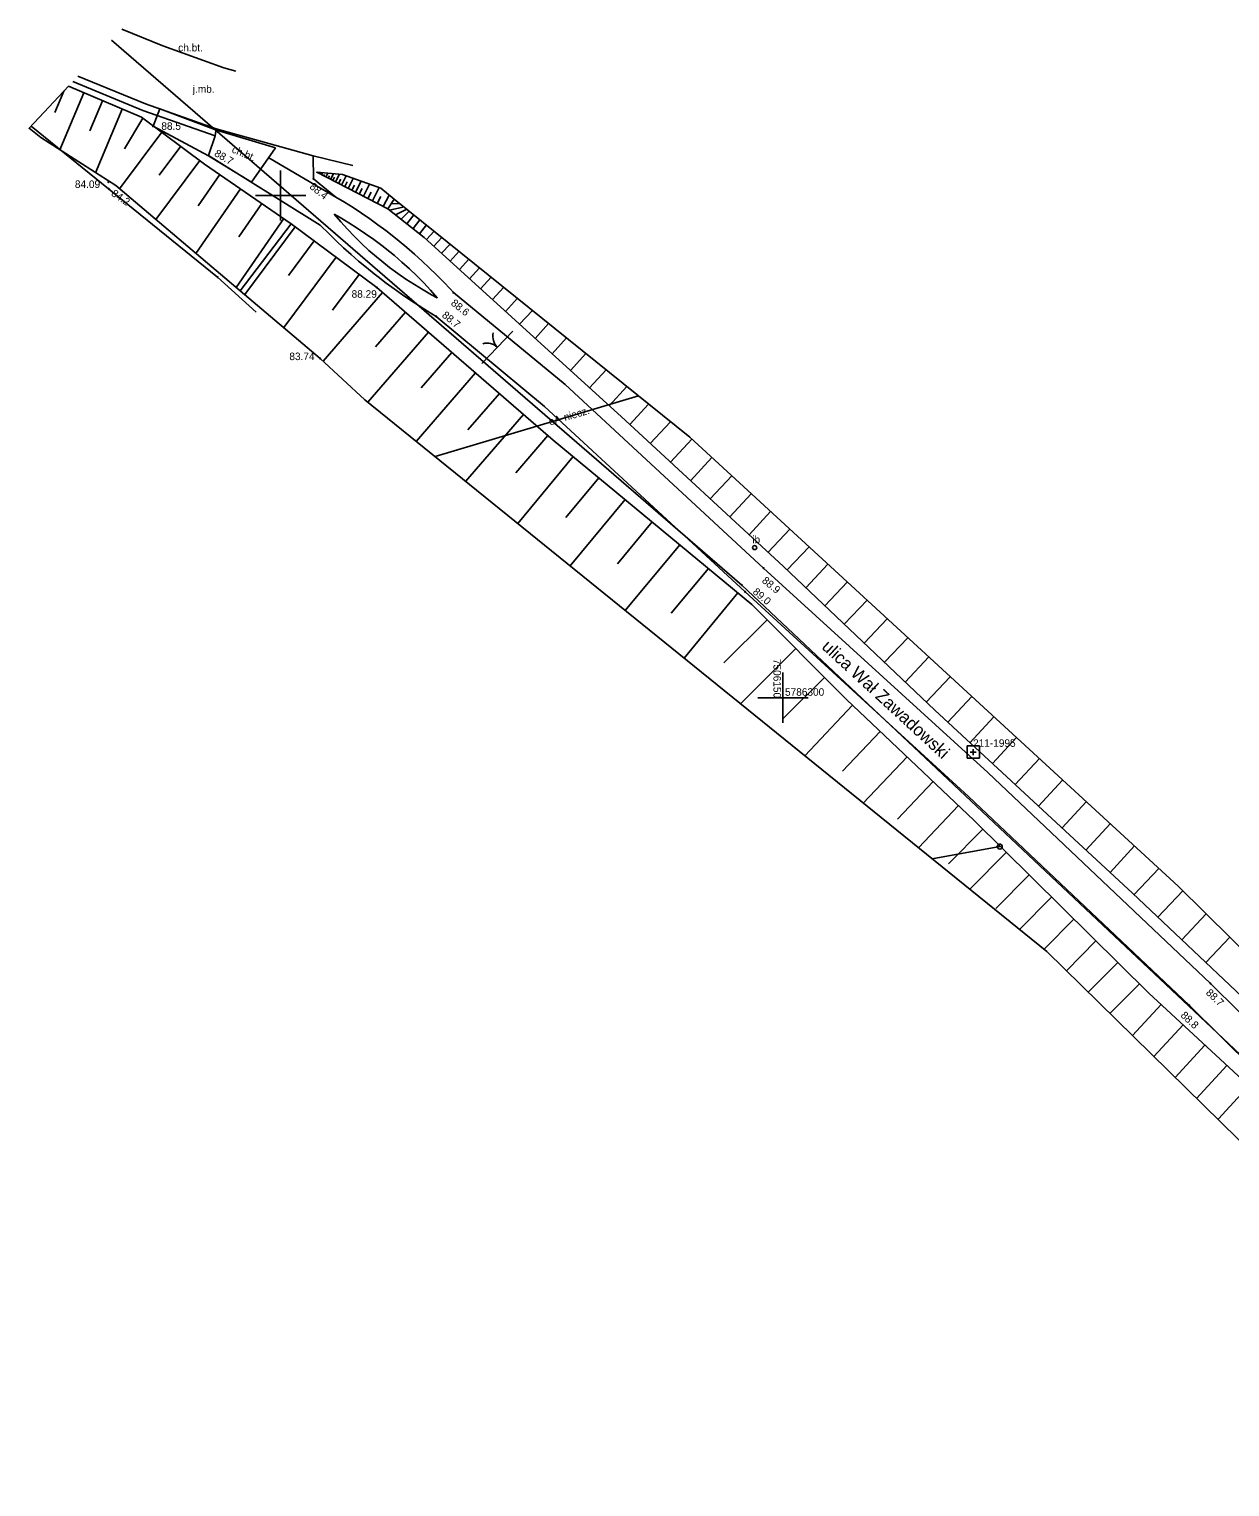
# Model space of a CAD drawing. Extents: x 7506075 to 7506993, y 5784375 to 5786367.
# Drawn here: x 7506075 to 7506194.5, y 5786221.4 to 5786366.6 of the extents above; entities that cross this region are included whole.
import ezdxf

# ---------------------------------------------------------------- set-up
doc = ezdxf.new("R2010")
doc.units = 0
for name, color, linetype in [('000 Inne (niezydentyfikowane)', 7, 'Continuous'), ('203-punkt graniczny', 7, 'Continuous'), ('216-obręb ewidencyjny', 7, 'Continuous'), ('218-kontur użytku gruntowego', 7, 'Continuous'), ('219-działka ewidencyjna', 7, 'Continuous'), ('994-Nazwa ulicy', 7, 'Continuous'), ('brama', 7, 'Continuous'), ('chodnik', 7, 'Continuous'), ('chodnik-Atr17', 7, 'Continuous'), ('inna budowla', 7, 'Continuous'), ('inna budowla-Atr17', 7, 'Continuous'), ('jezdnia', 7, 'Continuous'), ('jezdnia-Atr17', 7, 'Continuous'), ('krawężnik', 7, 'Continuous'), ('pikieta sztuczna', 7, 'Continuous'), ('pikieta sztuczna-Atr2', 7, 'Continuous'), ('przewód elektroenergetyczny podziemny', 7, 'Continuous'), ('przewód elektroenergetyczny podziemny-Atr1', 7, 'Continuous'), ('przewód telekomunikacyjny napowietrzny', 7, 'Continuous'), ('skarpa nieumocniona', 7, 'Continuous'), ('Szczegółowa osnowa geodezyjna pozioma', 7, 'Continuous'), ('Szczegółowa osnowa geodezyjna pozioma-Atr103', 7, 'Continuous'), ('słup przewodów napowietrznych', 7, 'Continuous'), ('wał przeciwpowodziowy', 7, 'Continuous'), ('Wstawianie ramki sekcyjnej z opisem', 7, 'Continuous')]:
    doc.layers.add(name, color=color, linetype=linetype)

# ---------------------------------------------------------------- blocks, each defined once
blk = doc.blocks.new('PW01')
blk.add_circle((0, 0), 0.045)
blk = doc.blocks.new('US25')
blk.add_circle((0, 0), 0.2)
blk = doc.blocks.new('US15')
blk.add_circle((0, 0), 0.25)
blk = doc.blocks.new('OK02')
for centre, start, end in [((-1.5, 0), 0, 60), ((1.5, 0), 120, 180)]:
    blk.add_arc(centre, 1.5, start, end)
blk = doc.blocks.new('203')
blk.add_circle((0, 0), 0.045)
blk = doc.blocks.new('OSSP')
for p, q in [((-0.626, 0.625), (-0.626, -0.625)), ((-0.626, 0.625), (-0.626, -0.625)), ((0.624, 0.625), (-0.626, 0.625)), ((0.624, 0.625), (-0.626, 0.625)), ((0.3, 0), (-0.3, 0)), ((0.3, 0), (-0.3, 0)), ((0, -0.3), (0, 0.3)), ((0, -0.3), (0, 0.3)), ((0.624, -0.625), (0.624, 0.625)), ((0.624, -0.625), (0.624, 0.625)), ((-0.626, -0.625), (0.624, -0.625)), ((-0.626, -0.625), (0.624, -0.625))]:
    blk.add_line(p, q)

msp = doc.modelspace()

# ---------------------------------------------------------------- linework, layer by layer
at = {"layer": '000 Inne (niezydentyfikowane)'}
for p, q in [((7506078.415, 5786360.382), (7506077.52, 5786358.27)), ((7506080.42, 5786360.22), (7506078.03, 5786354.54)), ((7506082.28, 5786359.44), (7506081.02, 5786356.44)), ((7506084.24, 5786358.61), (7506081.58, 5786352.27)), ((7506088.17, 5786356.3), (7506083.97, 5786350.66)), ((7506086.3, 5786357.7), (7506084.45, 5786354.66)), ((7506090.05, 5786354.9), (7506087.91, 5786352.02)), ((7506091.96, 5786353.48), (7506087.59, 5786347.61)), ((7506093.95, 5786352.09), (7506091.8, 5786348.97)), ((7506103.83, 5786352.19), (7506103.85, 5786352.24)), ((7506104.06, 5786352.07), (7506104.15, 5786352.26)), ((7506104.29, 5786351.96), (7506104.36, 5786352.1)), ((7506104.51, 5786351.84), (7506104.71, 5786352.21)), ((7506104.74, 5786351.72), (7506104.86, 5786351.95)), ((7506104.97, 5786351.6), (7506105.26, 5786352.16)), ((7506105.46, 5786351.35), (7506105.85, 5786352.11)), ((7506106.06, 5786351.04), (7506106.53, 5786351.95)), ((7506096, 5786350.67), (7506091.57, 5786344.24)), ((7506105.2, 5786351.49), (7506105.37, 5786351.81)), ((7506105.75, 5786351.2), (7506105.98, 5786351.63)), ((7506106.38, 5786350.88), (7506106.63, 5786351.35)), ((7506106.72, 5786350.7), (7506107.23, 5786351.7)), ((7506107.07, 5786350.52), (7506107.34, 5786351.04)), ((7506107.44, 5786350.33), (7506108.01, 5786351.42)), ((7506107.83, 5786350.13), (7506108.13, 5786350.7)), ((7506108.24, 5786349.92), (7506108.86, 5786351.12)), ((7506109.13, 5786349.46), (7506109.81, 5786350.79)), ((7506098.12, 5786349.21), (7506095.84, 5786345.89)), ((7506108.67, 5786349.69), (7506109, 5786350.33)), ((7506109.62, 5786349.2), (7506109.98, 5786349.9)), ((7506110.22, 5786348.9), (7506110.813, 5786350.048)), ((7506111.01, 5786349.2), (7506111.901, 5786349.171)), ((7506100.31, 5786347.7), (7506095.59, 5786340.84)), ((7506110.84, 5786348.53), (7506112.15, 5786348.83)), ((7506111.43, 5786348.07), (7506112.551, 5786348.647)), ((7506111.99, 5786347.63), (7506112.73, 5786348.38)), ((7506112.57, 5786347.18), (7506113.266, 5786348.07)), ((7506113.18, 5786346.7), (7506113.868, 5786347.585)), ((7506101.45, 5786346.89), (7506096.42, 5786340.14)), ((7506113.83, 5786346.19), (7506114.512, 5786347.066)), ((7506114.52, 5786345.62), (7506115.274, 5786346.451)), ((7506103.34, 5786345.48), (7506100.78, 5786342.05)), ((7506115.24, 5786344.96), (7506116.037, 5786345.836)), ((7506116.02, 5786344.25), (7506116.861, 5786345.172)), ((7506105.53, 5786343.85), (7506100.31, 5786336.85)), ((7506116.88, 5786343.48), (7506117.759, 5786344.449)), ((7506117.8, 5786342.63), (7506118.738, 5786343.659)), ((7506107.83, 5786342.14), (7506105.17, 5786338.57)), ((7506118.81, 5786341.72), (7506119.798, 5786342.804)), ((7506119.9, 5786340.72), (7506120.949, 5786341.877)), ((7506110.15, 5786340.34), (7506104.24, 5786333.5)), ((7506121.09, 5786339.64), (7506122.205, 5786340.864)), ((7506122.38, 5786338.46), (7506123.568, 5786339.765)), ((7506112.42, 5786338.38), (7506109.43, 5786334.92)), ((7506123.79, 5786337.18), (7506125.053, 5786338.568)), ((7506114.71, 5786336.39), (7506108.68, 5786329.414)), ((7506125.33, 5786335.78), (7506126.673, 5786337.262)), ((7506127.01, 5786334.25), (7506128.451, 5786335.829)), ((7506117.04, 5786334.38), (7506113.98, 5786330.84)), ((7506128.85, 5786332.58), (7506130.385, 5786334.27)), ((7506119.39, 5786332.35), (7506113.483, 5786325.528)), ((7506130.75, 5786330.85), (7506132.39, 5786332.653)), ((7506121.77, 5786330.29), (7506118.63, 5786326.67)), ((7506132.71, 5786329.06), (7506134.462, 5786330.983)), ((7506134.74, 5786327.2), (7506136.624, 5786329.24)), ((7506124.17, 5786328.21), (7506118.405, 5786321.545)), ((7506136.79, 5786325.31), (7506138.802, 5786327.484)), ((7506126.61, 5786326.1), (7506123.4, 5786322.39)), ((7506138.81, 5786323.44), (7506140.936, 5786325.74)), ((7506129.11, 5786324.01), (7506123.594, 5786317.346)), ((7506140.8, 5786321.61), (7506142.925, 5786323.912)), ((7506131.66, 5786321.9), (7506128.39, 5786317.94)), ((7506142.76, 5786319.8), (7506144.891, 5786322.103)), ((7506144.71, 5786318), (7506146.836, 5786320.315)), ((7506134.28, 5786319.74), (7506128.813, 5786313.124)), ((7506146.63, 5786316.23), (7506148.763, 5786318.543)), ((7506136.97, 5786317.52), (7506133.52, 5786313.35)), ((7506148.53, 5786314.48), (7506150.666, 5786316.794)), ((7506139.72, 5786315.24), (7506134.301, 5786308.683)), ((7506150.41, 5786312.73), (7506152.589, 5786315.025)), ((7506142.57, 5786312.88), (7506138.87, 5786308.41)), ((7506152.27, 5786310.96), (7506154.479, 5786313.287)), ((7506154.16, 5786309.16), (7506156.402, 5786311.519)), ((7506145.52, 5786310.45), (7506140.153, 5786303.948)), ((7506156.1, 5786307.32), (7506158.371, 5786309.708)), ((7506148.44, 5786307.76), (7506144.12, 5786303.47)), ((7506158.08, 5786305.44), (7506160.379, 5786307.862)), ((7506160.09, 5786303.53), (7506162.425, 5786305.98)), ((7506151.28, 5786304.9), (7506145.759, 5786299.411)), ((7506162.15, 5786301.57), (7506164.514, 5786304.059)), ((7506154.14, 5786302.03), (7506149.99, 5786297.91)), ((7506164.25, 5786299.57), (7506166.648, 5786302.097)), ((7506166.41, 5786297.56), (7506168.786, 5786300.131)), ((7506156.93, 5786299.26), (7506152.161, 5786294.232)), ((7506168.61, 5786295.52), (7506170.99, 5786298.104)), ((7506159.68, 5786296.65), (7506155.92, 5786292.68)), ((7506170.84, 5786293.46), (7506173.232, 5786296.042)), ((7506162.35, 5786294.11), (7506157.992, 5786289.513)), ((7506173.12, 5786291.35), (7506175.515, 5786293.943)), ((7506164.95, 5786291.65), (7506161.4, 5786287.91)), ((7506175.43, 5786289.21), (7506177.832, 5786291.812)), ((7506177.77, 5786287.04), (7506180.181, 5786289.652)), ((7506167.47, 5786289.26), (7506163.489, 5786285.065)), ((7506169.9, 5786286.92), (7506166.47, 5786283.46)), ((7506180.15, 5786284.84), (7506182.57, 5786287.455)), ((7506182.55, 5786282.62), (7506184.972, 5786285.246)), ((7506172.23, 5786284.62), (7506168.591, 5786280.937)), ((7506174.5, 5786282.37), (7506171.19, 5786279.03)), ((7506184.94, 5786280.41), (7506187.401, 5786283.013)), ((7506176.74, 5786280.16), (7506173.544, 5786276.93)), ((7506187.32, 5786278.16), (7506189.798, 5786280.778)), ((7506178.96, 5786277.97), (7506175.978, 5786274.96)), ((7506189.7, 5786275.91), (7506192.129, 5786278.479)), ((7506181.15, 5786275.8), (7506178.205, 5786272.823)), ((7506192.09, 5786273.65), (7506194.469, 5786276.17)), ((7506183.32, 5786273.65), (7506180.384, 5786270.686)), ((7506185.47, 5786271.53), (7506182.542, 5786268.57)), ((7506187.64, 5786269.47), (7506184.776, 5786266.379)), ((7506189.82, 5786267.44), (7506186.904, 5786264.293)), ((7506192, 5786265.42), (7506189.027, 5786262.211)), ((7506194.19, 5786263.4), (7506191.157, 5786260.122)), ((7506196.37, 5786261.38), (7506193.33, 5786258.1))]:
    msp.add_line(p, q, dxfattribs=at)
at = {"layer": '216-obręb ewidencyjny'}
for points in [[(7506145.91, 5786311.21), (7506083.164, 5786365.472)], [(7506206.92, 5786253.74), (7506145.91, 5786311.21)]]:
    msp.add_lwpolyline(points, dxfattribs=at)
at = {"layer": '218-kontur użytku gruntowego'}
for points in [[(7506083.164, 5786365.472), (7506145.91, 5786311.21)], [(7506145.91, 5786311.21), (7506206.92, 5786253.74)]]:
    msp.add_lwpolyline(points, dxfattribs=at)
at = {"layer": '219-działka ewidencyjna'}
for points in [[(7506145.91, 5786311.21), (7506083.164, 5786365.472)], [(7506083.164, 5786365.472), (7506145.91, 5786311.21)], [(7506093.73, 5786341.88), (7506075.159, 5786356.892)], [(7506097.577, 5786338.397), (7506093.73, 5786341.88)], [(7506206.92, 5786253.74), (7506145.91, 5786311.21)], [(7506145.91, 5786311.21), (7506206.92, 5786253.74)]]:
    msp.add_lwpolyline(points, dxfattribs=at)
at = {"layer": 'brama'}
msp.add_lwpolyline([(7506120.04, 5786333.29), (7506123.12, 5786336.49)], dxfattribs=at)
at = {"layer": 'chodnik'}
for points in [[(7506095.533, 5786362.366), (7506094.36, 5786362.72), (7506088.27, 5786364.91), (7506084.18, 5786366.56)], [(7506093.48, 5786355.95), (7506086.29, 5786358.46), (7506079.31, 5786361.341)], [(7506079.815, 5786361.883), (7506086.55, 5786359.11), (7506093.59, 5786356.65), (7506093.48, 5786355.95)]]:
    msp.add_lwpolyline(points, dxfattribs=at)
msp.add_lwpolyline([(7506099.5, 5786354.74), (7506097.111, 5786351.318), (7506092.83, 5786353.96), (7506087.3, 5786356.9), (7506087.99, 5786358.64), (7506093.62, 5786356.51)], close=True, dxfattribs=at)
at = {"layer": 'jezdnia'}
msp.add_line((7506098.818, 5786353.763), (7506105.51, 5786349.85), dxfattribs=at)
for points in [[(7506084.18, 5786366.56), (7506088.27, 5786364.91), (7506094.36, 5786362.72), (7506095.533, 5786362.366)], [(7506107.186, 5786352.972), (7506103.24, 5786353.94), (7506093.59, 5786356.65), (7506086.55, 5786359.11), (7506079.815, 5786361.883)], [(7506212.75, 5786247.31), (7506190.42, 5786269.4), (7506168.47, 5786290.18), (7506146.24, 5786310.54), (7506126.27, 5786328.98), (7506115.49, 5786337.97), (7506114.63, 5786338.48), (7506113.79, 5786339.01), (7506112.95, 5786339.56), (7506112.12, 5786340.12), (7506111.3, 5786340.7), (7506110.5, 5786341.29), (7506109.7, 5786341.89), (7506109.31, 5786342.2), (7506108.53, 5786342.83), (7506107.76, 5786343.47), (7506107.01, 5786344.12), (7506106.27, 5786344.79), (7506105.54, 5786345.48), (7506104.82, 5786346.17), (7506103.95, 5786347.05), (7506092.83, 5786353.99), (7506093.48, 5786355.95), (7506093.59, 5786356.65), (7506103.24, 5786353.94), (7506103.28, 5786351.65), (7506105.51, 5786349.85), (7506106.37, 5786349.33), (7506107.21, 5786348.8), (7506108.04, 5786348.25), (7506108.87, 5786347.68), (7506109.68, 5786347.09), (7506110.48, 5786346.5), (7506111.27, 5786345.88), (7506111.8, 5786345.45), (7506112.57, 5786344.81), (7506113.32, 5786344.15), (7506114.07, 5786343.48), (7506114.79, 5786342.8), (7506115.51, 5786342.1), (7506116.21, 5786341.39), (7506116.9, 5786340.66), (7506117.19, 5786340.34), (7506128.33, 5786331.2), (7506148.07, 5786312.91), (7506170.38, 5786292.56), (7506192.56, 5786271.55), (7506214.92, 5786249.44)]]:
    msp.add_lwpolyline(points, dxfattribs=at)
msp.add_lwpolyline([(7506105.33, 5786348.14), (7506105.98, 5786347.38), (7506106.65, 5786346.64), (7506107.34, 5786345.92), (7506108.06, 5786345.22), (7506108.79, 5786344.54), (7506109.55, 5786343.88), (7506110.06, 5786343.46), (7506110.85, 5786342.84), (7506111.65, 5786342.25), (7506112.47, 5786341.68), (7506113.31, 5786341.13), (7506114.17, 5786340.61), (7506115.03, 5786340.12), (7506115.59, 5786339.82), (7506114.92, 5786340.57), (7506114.24, 5786341.3), (7506113.54, 5786342.01), (7506112.81, 5786342.7), (7506112.07, 5786343.37), (7506111.32, 5786344.02), (7506110.86, 5786344.4), (7506110.08, 5786345.02), (7506109.28, 5786345.62), (7506108.46, 5786346.2), (7506107.63, 5786346.76), (7506106.78, 5786347.29), (7506105.93, 5786347.8)], close=True, dxfattribs=at)
at = {"layer": 'krawężnik'}
for points in [[(7506084.18, 5786366.56), (7506088.27, 5786364.91), (7506094.36, 5786362.72), (7506095.533, 5786362.366)], [(7506093.59, 5786356.65), (7506086.55, 5786359.11), (7506079.815, 5786361.883)]]:
    msp.add_lwpolyline(points, dxfattribs=at)
at = {"layer": 'przewód elektroenergetyczny podziemny'}
msp.add_lwpolyline([(7506115.364, 5786324.006), (7506135.627, 5786330.044)], dxfattribs=at)
at = {"layer": 'przewód telekomunikacyjny napowietrzny'}
msp.add_lwpolyline([(7506171.58, 5786285.18), (7506164.844, 5786283.969)], dxfattribs=at)
at = {"layer": 'skarpa nieumocniona'}
for points in [[(7506086.15, 5786357.81), (7506092.43, 5786353.13), (7506101.05, 5786347.19), (7506095.98, 5786340.51), (7506083.6, 5786350.98), (7506076.12, 5786355.76), (7506074.97, 5786356.69), (7506078.87, 5786360.87)], [(7506106.15, 5786352.08), (7506109.96, 5786350.73), (7506111.31, 5786349.65), (7506110.66, 5786348.67), (7506103.6, 5786352.31)]]:
    msp.add_lwpolyline(points, close=True, dxfattribs=at)
at = {"layer": 'wał przeciwpowodziowy'}
for points in [[(7506140.73, 5786325.93), (7506189.34, 5786281.23), (7506221.23, 5786249.77), (7506250.23, 5786220.27), (7506273.28, 5786195.13), (7506271.06, 5786193.16), (7506255.61, 5786208.85), (7506244.73, 5786220.78), (7506228.2, 5786237.69), (7506215.87, 5786250.01), (7506200.56, 5786265.64), (7506184.79, 5786280.55), (7506165.11, 5786298.76), (7506150.05, 5786313.07), (7506133.89, 5786327.99), (7506114.29, 5786345.83), (7506110.66, 5786348.67), (7506111.31, 5786349.65)], [(7506140.73, 5786325.93), (7506189.34, 5786281.23), (7506221.23, 5786249.77), (7506250.23, 5786220.27), (7506273.28, 5786195.13), (7506271.06, 5786193.16), (7506255.61, 5786208.85), (7506244.73, 5786220.78), (7506228.2, 5786237.69), (7506215.87, 5786250.01), (7506200.56, 5786265.64), (7506184.79, 5786280.55), (7506165.11, 5786298.76), (7506150.05, 5786313.07), (7506133.89, 5786327.99), (7506114.29, 5786345.83), (7506110.66, 5786348.67), (7506111.31, 5786349.65)], [(7506109.56, 5786340.85), (7506127.14, 5786325.64), (7506146.91, 5786309.3), (7506156.33, 5786299.83), (7506169.02, 5786287.79), (7506186.4, 5786270.61), (7506200.62, 5786257.45), (7506209.49, 5786248.95), (7506226.78, 5786231.34), (7506243.05, 5786215.67), (7506258.34, 5786201.07), (7506261.09, 5786197.23), (7506267.45, 5786190.29), (7506263.46, 5786186.75), (7506261.87, 5786188.63), (7506214.35, 5786237.38), (7506176.25, 5786274.74), (7506108.37, 5786329.67), (7506103.95, 5786333.77), (7506095.98, 5786340.51), (7506101.05, 5786347.19)], [(7506109.56, 5786340.85), (7506127.14, 5786325.64), (7506146.91, 5786309.3), (7506156.33, 5786299.83), (7506169.02, 5786287.79), (7506186.4, 5786270.61), (7506200.62, 5786257.45), (7506209.49, 5786248.95), (7506226.78, 5786231.34), (7506243.05, 5786215.67), (7506258.34, 5786201.07), (7506261.09, 5786197.23), (7506267.45, 5786190.29), (7506263.46, 5786186.75), (7506261.87, 5786188.63), (7506214.35, 5786237.38), (7506176.25, 5786274.74), (7506108.37, 5786329.67), (7506103.95, 5786333.77), (7506095.98, 5786340.51), (7506101.05, 5786347.19)]]:
    msp.add_lwpolyline(points, close=True, dxfattribs=at)
at = {"layer": 'Wstawianie ramki sekcyjnej z opisem'}
for points in [[(7506100, 5786347.5), (7506100, 5786352.5)], [(7506097.5, 5786350), (7506102.5, 5786350)], [(7506150, 5786297.5), (7506150, 5786302.5)], [(7506147.5, 5786300), (7506152.5, 5786300)]]:
    msp.add_lwpolyline(points, dxfattribs=at)

# ---------------------------------------------------------------- block references
at = {"layer": '203-punkt graniczny'}
for p in [(7506093.73, 5786341.88), (7506145.91, 5786311.21)]:
    msp.add_blockref('203', p, dxfattribs=at)
at = {"layer": 'brama', "rotation": 46.09499999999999}
msp.add_blockref('OK02', (7506121.58, 5786334.89), dxfattribs=at)
at = {"layer": 'inna budowla'}
msp.add_blockref('US25', (7506147.18, 5786314.95), dxfattribs=at)
at = {"layer": 'pikieta sztuczna'}
for p in [(7506087.3, 5786356.9), (7506092.83, 5786353.99), (7506082.85, 5786351.34), (7506082.9, 5786350.66), (7506103.28, 5786351.65), (7506109.56, 5786340.85), (7506117.19, 5786340.34), (7506115.49, 5786337.97), (7506103.95, 5786333.77), (7506148.07, 5786312.91), (7506146.24, 5786310.54), (7506192.56, 5786271.55), (7506190.42, 5786269.4)]:
    msp.add_blockref('PW01', p, dxfattribs=at)
at = {"layer": 'Szczegółowa osnowa geodezyjna pozioma'}
msp.add_blockref('OSSP', (7506168.94, 5786294.6), dxfattribs=at)
at = {"layer": 'słup przewodów napowietrznych'}
msp.add_blockref('US15', (7506171.58, 5786285.18), dxfattribs=at)

# ---------------------------------------------------------------- texts
at = {"layer": '994-Nazwa ulicy'}
msp.add_text('ulica Wał Zawadowski', height=1.25, rotation=317.355, dxfattribs=at).set_placement((7506153.77, 5786304.96))
at = {"layer": 'chodnik-Atr17'}
msp.add_text('ch.bt.', height=0.75, dxfattribs=at).set_placement((7506089.805, 5786364.345))
msp.add_text('ch.bt.', height=0.75, rotation=337.158, dxfattribs=at).set_placement((7506095.071, 5786354.32))
at = {"layer": 'inna budowla-Atr17'}
msp.add_text('ib', height=0.75, dxfattribs=at).set_placement((7506146.942, 5786315.375))
at = {"layer": 'jezdnia-Atr17'}
msp.add_text('j.mb.', height=0.75, dxfattribs=at).set_placement((7506091.254, 5786360.227))
msp.add_text('j.mb.', height=0.75, dxfattribs=at).set_placement((7506091.254, 5786360.227))
at = {"layer": 'pikieta sztuczna-Atr2'}
for s, p in [('88.5', (7506088.125, 5786356.537)), ('84.09', (7506079.523, 5786350.752)), ('88.29', (7506107.062, 5786339.821)), ('83.74', (7506100.868, 5786333.614))]:
    msp.add_text(s, height=0.75, dxfattribs=at).set_placement(p)
for s, rotation, p in [('88.7', 329.848, (7506093.33, 5786353.99)), ('84.2', 325.601, (7506083.07, 5786350.046)), ('88.4', 321.361, (7506102.812, 5786350.764)), ('88.6', 321.214, (7506116.884, 5786339.169)), ('88.7', 321.007, (7506115.99, 5786337.97)), ('88.9', 320.34, (7506147.84, 5786311.555)), ('89.0', 319.699, (7506146.92, 5786310.445)), ('88.7', 316.682, (7506192.027, 5786270.56)), ('88.8', 316.714, (7506189.516, 5786268.313))]:
    msp.add_text(s, height=0.75, rotation=rotation, dxfattribs=at).set_placement(p)
at = {"layer": 'przewód elektroenergetyczny podziemny-Atr1'}
msp.add_text('eA-niecz.', height=0.75, rotation=16.592, dxfattribs=at).set_placement((7506126.807, 5786327.095))
at = {"layer": 'Szczegółowa osnowa geodezyjna pozioma-Atr103'}
msp.add_text('211-1995', height=0.75, dxfattribs=at).set_placement((7506168.917, 5786295.117))
at = {"layer": 'Wstawianie ramki sekcyjnej z opisem'}
for s, rotation, p in [('7506150', 270, (7506149.05, 5786303.868)), ('5786300', 0.001, (7506150.2, 5786300.2))]:
    msp.add_text(s, height=0.75, rotation=rotation, dxfattribs=at).set_placement(p)

doc.saveas('drawing.dxf')
